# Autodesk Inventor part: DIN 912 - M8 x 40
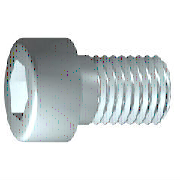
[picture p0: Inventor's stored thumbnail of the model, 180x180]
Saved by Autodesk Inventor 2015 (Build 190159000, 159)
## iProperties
Created: 2014-02
Part Number: DIN 912 - M8 x 40
Material: Steel, Mild
Description: Cylinder Head Cap Screw
Document SubType Name: Modeling
Standard: DIN 912
Designer: TREINA6
Standards Organization: DIN
Language: en-US
Size Designation: M8 x 40
Categories: <MemberInstance><Categories><Category DisplayName="Fasteners" InternalName="e4da775c-781d-43d5-af7c-5136215cf5a6" Mnemonic="FSTN"><Category DisplayName="Bolts"
Density: 1 g/cm^3
Appearance: Semi-Polished
IsCustomPart: 1
Author: TREINA6
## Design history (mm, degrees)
sketch "Sketch1"
  geometry: L1 (-2, 0)-(40, 0); L2 (40, 0)-(40, 4); L3 (40, 4)-(12, 4); L4 (12, 4)-(11.233, 4); L5 (11.233, 4)-(0, 4); L6 (0, 4)-(0, 6.5); L7 (0, 6.5)-(-8, 6.5); L8 (-8, 6.5)-(-8, 3.464); L9 (-8, 3.464)-(-4, 3.464); L10 (-4, 3.464)-(-2, 0); L11 (-17.6, 0)-(49.6, 0) reference; L12 (0, -1.3)-(0, 7.8) reference; L13 (12, 4)-(0, 4)
  constraints: 22 end point, 6 parallel, 2 collinear, 2 perpendicular, 1 horizontal, 1 point on line
  dimensions: "d1" = 28 distance from line of L3.end L2 (= GEL); "d2" = 0.76691 distance of L4.end L3.end (computed from GAL); "d3" = 8 distance between parallel lines of L8 L6 (= KOH); "d4" = 4 distance of L8.end L9.end (= INTI); "d5" = 60 deg angle of L10 L1; "d6" = 8 diameter of L3 L1 (= GD); "d7" = 8 diameter of L5 L1 (= BDM); "d8" = 6.9282 diameter of L9 L1 (= 1.1547 x SW); "d9" = 13 diameter of L7 L1 (= KOD); "d26" = 40 distance between parallel lines of L12 L2 (= NLG)
revolve "Body" sketch "Sketch1" stored, may be unused: angle "d10" = 90 deg
sketch "Sketch2"
  geometry: L1 (0, -9.1)-(0, 9.1) reference; L2 (-9.1, 0)-(9.1, 0) reference; L3 (3.464, 0)-(1.732, -3); L4 (1.732, -3)-(-1.732, -3); L5 (-1.732, -3)-(-3.464, 0); L6 (-3.464, 0)-(-1.732, 3); L7 (-1.732, 3)-(1.732, 3); L8 (1.732, 3)-(3.464, 0); 2 further points
  constraints: 12 end point, 1 coincident, 1 horizontal alignment, 1 point on line, 12 other
extrude "Slot" join sketch "Sketch2" stored distance "d11" = 10; taper "d12" = 0 deg
workplane "Work Plane1"
fillet "Fillet2" dims "d30" = 0.4 (= R)
body "Solid1"
fillet "Fillet1" dims "d17" = 0.8 (= RR)
feature "Thread" dims "d13" = 28 (= GEL), "d14" = 0
chamfer "Chamfer1" distance "d15" = 0.76681 (= -0.5 x SPD + 0.5 x GD); stored, may be unused: second distance "d16" = 0.76681 (= GUL), angle "d27" = 45 deg
other parameters: "GD" = 8 (= NND) [user parameter; used in 2 equation terms], "NLG" = 40 [user parameter; used in 1 equation term], "GEL" = 28 [user parameter; used in 2 equation terms], "KOD" = 13 [user parameter; used in 1 equation term], "KOH" = 8 [user parameter; used in 1 equation term], "INTI" = 4 [user parameter; used in 1 equation term], "GAL" = 0.76681 (= 0.61345 x PTC) [user parameter; used in 1 equation term], "GUL" = 0.76681 (= 0.61345 x PTC) [user parameter; used in 1 equation term], "BDM" = 8 (= NND) [user parameter; used in 1 equation term], "SW" = 6 [user parameter; used in 2 equation terms], "RR" = 0.8 [user parameter; used in 1 equation term], "SPD" = 6.46637 (= NND - 1.2269 x PTC) [user parameter; used in 1 equation term], "d19" = 0, "d28" = 0, "d29" = 0, "R" = 0.4 [user parameter; used in 1 equation term], "TOA" = 30 deg [user parameter], "GD1" = 6.46637 (= THREADDIA - 1.2269 x PTC) [user parameter], "THREADDIA" = 8 [user parameter; used in 1 equation term], "FAWI" = 45 deg [user parameter], "ANG" = 120 deg [user parameter], "TPU" = 8 (computed from PTC) [user parameter], "PTC" = 1.25 [user parameter; used in 5 equation terms], "NND" = 8 [user parameter; used in 3 equation terms], "E0" = 6.93 (= 1.155 x SW) [user parameter]
